(* Logix 5000 project; controller LinePLC1 vendor 1 type 14 code 154 rev 32.11; software revision 32.03; part 2 of 3 *)

ADD_ON_INSTRUCTION FB_ISCCAM_IO_Read   (* revision 1.0, vendor INTRALOX *)
VAR_IN_OUT
   iRawData_Receive : dt_ISCCAM_IO_IN; {required}
   oData_Receive : dt_ISC_CAM_Receive; {required}
END_VAR

ROUTINE Logic   (* ladder *)
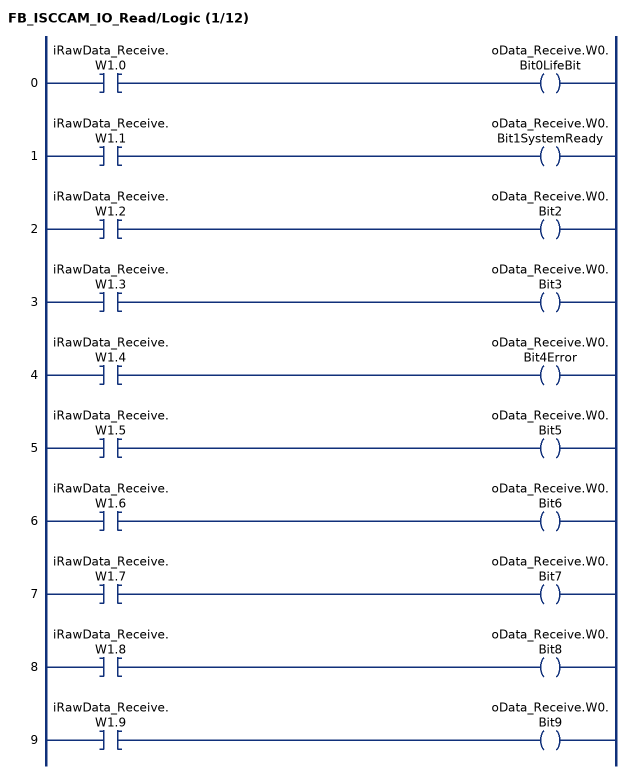
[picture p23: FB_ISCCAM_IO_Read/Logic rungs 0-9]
   0: XIC(iRawData_Receive.W1.0)OTE(oData_Receive.W0.Bit0LifeBit);
   1: XIC(iRawData_Receive.W1.1)OTE(oData_Receive.W0.Bit1SystemReady);
   2: XIC(iRawData_Receive.W1.2)OTE(oData_Receive.W0.Bit2);
   3: XIC(iRawData_Receive.W1.3)OTE(oData_Receive.W0.Bit3);
   4: XIC(iRawData_Receive.W1.4)OTE(oData_Receive.W0.Bit4Error);
   5: XIC(iRawData_Receive.W1.5)OTE(oData_Receive.W0.Bit5);
   6: XIC(iRawData_Receive.W1.6)OTE(oData_Receive.W0.Bit6);
   7: XIC(iRawData_Receive.W1.7)OTE(oData_Receive.W0.Bit7);
   8: XIC(iRawData_Receive.W1.8)OTE(oData_Receive.W0.Bit8);
   9: XIC(iRawData_Receive.W1.9)OTE(oData_Receive.W0.Bit9);
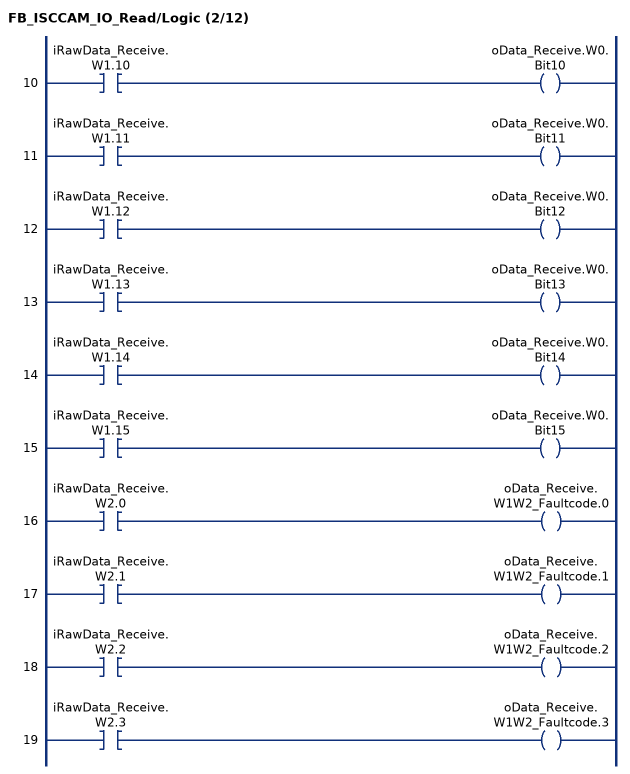
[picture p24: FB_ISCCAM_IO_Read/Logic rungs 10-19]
   10: XIC(iRawData_Receive.W1.10)OTE(oData_Receive.W0.Bit10);
   11: XIC(iRawData_Receive.W1.11)OTE(oData_Receive.W0.Bit11);
   12: XIC(iRawData_Receive.W1.12)OTE(oData_Receive.W0.Bit12);
   13: XIC(iRawData_Receive.W1.13)OTE(oData_Receive.W0.Bit13);
   14: XIC(iRawData_Receive.W1.14)OTE(oData_Receive.W0.Bit14);
   15: XIC(iRawData_Receive.W1.15)OTE(oData_Receive.W0.Bit15);
   16: XIC(iRawData_Receive.W2.0)OTE(oData_Receive.W1W2_Faultcode.0);
   17: XIC(iRawData_Receive.W2.1)OTE(oData_Receive.W1W2_Faultcode.1);
   18: XIC(iRawData_Receive.W2.2)OTE(oData_Receive.W1W2_Faultcode.2);
   19: XIC(iRawData_Receive.W2.3)OTE(oData_Receive.W1W2_Faultcode.3);
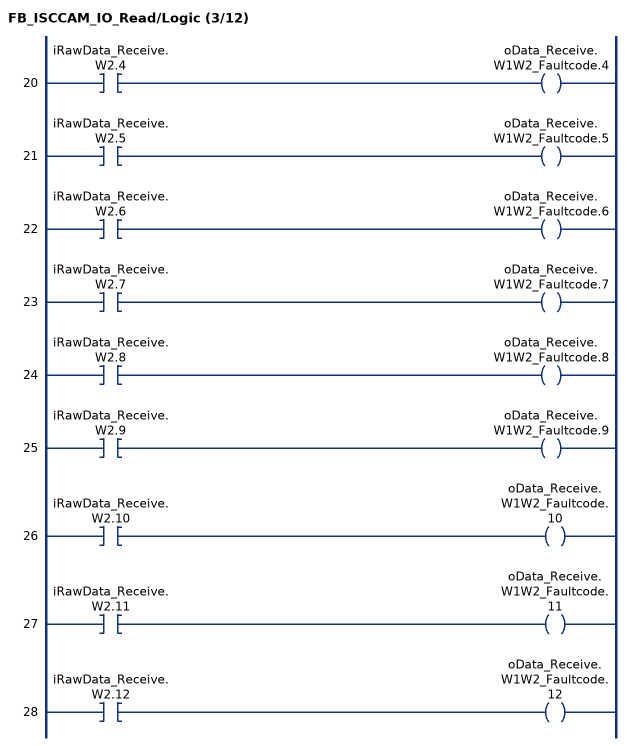
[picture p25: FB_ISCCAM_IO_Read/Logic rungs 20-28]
   20: XIC(iRawData_Receive.W2.4)OTE(oData_Receive.W1W2_Faultcode.4);
   21: XIC(iRawData_Receive.W2.5)OTE(oData_Receive.W1W2_Faultcode.5);
   22: XIC(iRawData_Receive.W2.6)OTE(oData_Receive.W1W2_Faultcode.6);
   23: XIC(iRawData_Receive.W2.7)OTE(oData_Receive.W1W2_Faultcode.7);
   24: XIC(iRawData_Receive.W2.8)OTE(oData_Receive.W1W2_Faultcode.8);
   25: XIC(iRawData_Receive.W2.9)OTE(oData_Receive.W1W2_Faultcode.9);
   26: XIC(iRawData_Receive.W2.10)OTE(oData_Receive.W1W2_Faultcode.10);
   27: XIC(iRawData_Receive.W2.11)OTE(oData_Receive.W1W2_Faultcode.11);
   28: XIC(iRawData_Receive.W2.12)OTE(oData_Receive.W1W2_Faultcode.12);
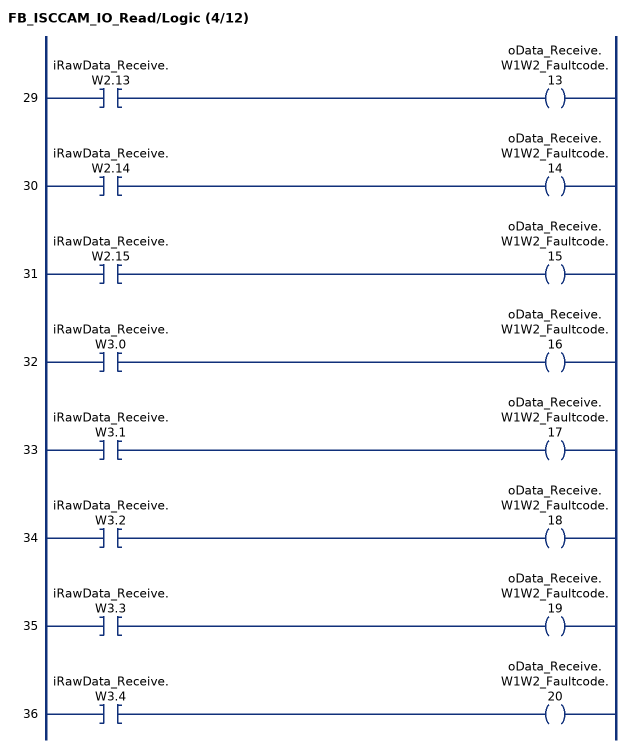
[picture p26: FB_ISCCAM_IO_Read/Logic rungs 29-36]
   29: XIC(iRawData_Receive.W2.13)OTE(oData_Receive.W1W2_Faultcode.13);
   30: XIC(iRawData_Receive.W2.14)OTE(oData_Receive.W1W2_Faultcode.14);
   31: XIC(iRawData_Receive.W2.15)OTE(oData_Receive.W1W2_Faultcode.15);
   32: XIC(iRawData_Receive.W3.0)OTE(oData_Receive.W1W2_Faultcode.16);
   33: XIC(iRawData_Receive.W3.1)OTE(oData_Receive.W1W2_Faultcode.17);
   34: XIC(iRawData_Receive.W3.2)OTE(oData_Receive.W1W2_Faultcode.18);
   35: XIC(iRawData_Receive.W3.3)OTE(oData_Receive.W1W2_Faultcode.19);
   36: XIC(iRawData_Receive.W3.4)OTE(oData_Receive.W1W2_Faultcode.20);
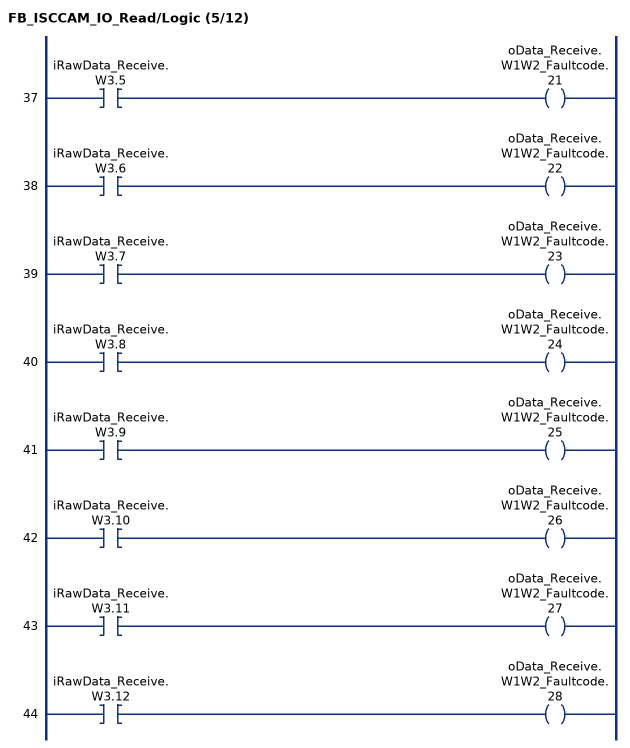
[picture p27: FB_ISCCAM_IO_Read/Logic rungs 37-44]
   37: XIC(iRawData_Receive.W3.5)OTE(oData_Receive.W1W2_Faultcode.21);
   38: XIC(iRawData_Receive.W3.6)OTE(oData_Receive.W1W2_Faultcode.22);
   39: XIC(iRawData_Receive.W3.7)OTE(oData_Receive.W1W2_Faultcode.23);
   40: XIC(iRawData_Receive.W3.8)OTE(oData_Receive.W1W2_Faultcode.24);
   41: XIC(iRawData_Receive.W3.9)OTE(oData_Receive.W1W2_Faultcode.25);
   42: XIC(iRawData_Receive.W3.10)OTE(oData_Receive.W1W2_Faultcode.26);
   43: XIC(iRawData_Receive.W3.11)OTE(oData_Receive.W1W2_Faultcode.27);
   44: XIC(iRawData_Receive.W3.12)OTE(oData_Receive.W1W2_Faultcode.28);
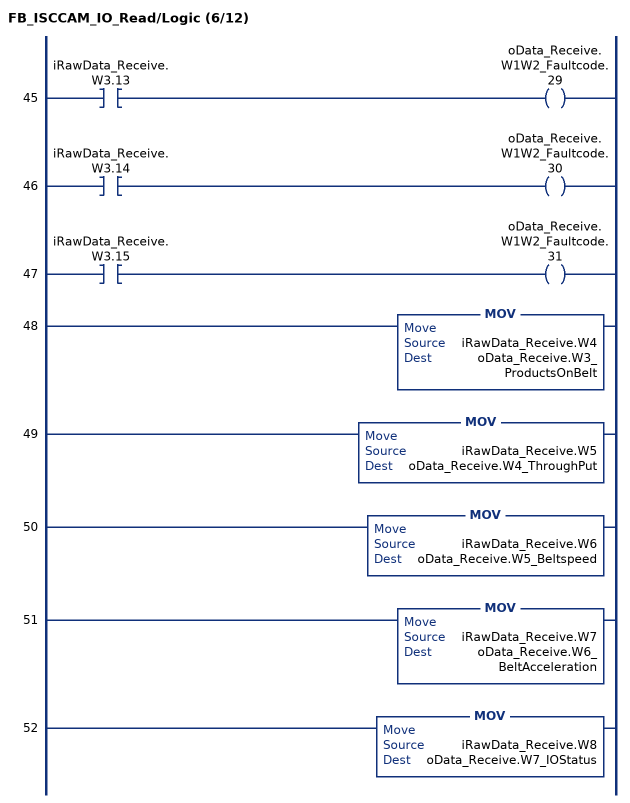
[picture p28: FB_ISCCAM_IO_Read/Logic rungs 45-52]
   45: XIC(iRawData_Receive.W3.13)OTE(oData_Receive.W1W2_Faultcode.29);
   46: XIC(iRawData_Receive.W3.14)OTE(oData_Receive.W1W2_Faultcode.30);
   47: XIC(iRawData_Receive.W3.15)OTE(oData_Receive.W1W2_Faultcode.31);
   48: MOV(iRawData_Receive.W4,oData_Receive.W3_ProductsOnBelt);
   49: MOV(iRawData_Receive.W5,oData_Receive.W4_ThroughPut);
   50: MOV(iRawData_Receive.W6,oData_Receive.W5_Beltspeed);
   51: MOV(iRawData_Receive.W7,oData_Receive.W6_BeltAcceleration);
   52: MOV(iRawData_Receive.W8,oData_Receive.W7_IOStatus);
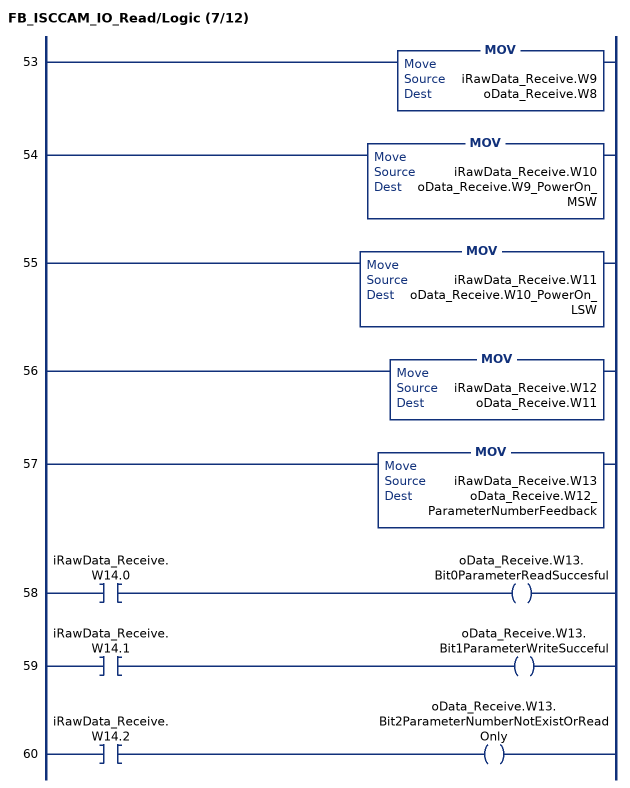
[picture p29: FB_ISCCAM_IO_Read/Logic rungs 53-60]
   53: MOV(iRawData_Receive.W9,oData_Receive.W8);
   54: MOV(iRawData_Receive.W10,oData_Receive.W9_PowerOn_MSW);
   55: MOV(iRawData_Receive.W11,oData_Receive.W10_PowerOn_LSW);
   56: MOV(iRawData_Receive.W12,oData_Receive.W11);
   57: MOV(iRawData_Receive.W13,oData_Receive.W12_ParameterNumberFeedback);
   58: XIC(iRawData_Receive.W14.0)OTE(oData_Receive.W13.Bit0ParameterReadSuccesful);
   59: XIC(iRawData_Receive.W14.1)OTE(oData_Receive.W13.Bit1ParameterWriteSucceful);
   60: XIC(iRawData_Receive.W14.2)OTE(oData_Receive.W13.Bit2ParameterNumberNotExistOrReadOnly);
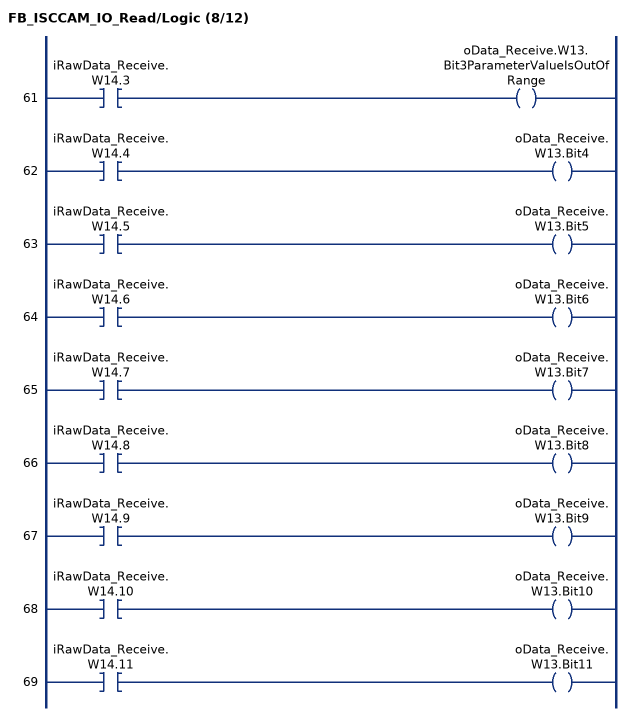
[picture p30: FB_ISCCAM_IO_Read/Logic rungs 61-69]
   61: XIC(iRawData_Receive.W14.3)OTE(oData_Receive.W13.Bit3ParameterValueIsOutOfRange);
   62: XIC(iRawData_Receive.W14.4)OTE(oData_Receive.W13.Bit4);
   63: XIC(iRawData_Receive.W14.5)OTE(oData_Receive.W13.Bit5);
   64: XIC(iRawData_Receive.W14.6)OTE(oData_Receive.W13.Bit6);
   65: XIC(iRawData_Receive.W14.7)OTE(oData_Receive.W13.Bit7);
   66: XIC(iRawData_Receive.W14.8)OTE(oData_Receive.W13.Bit8);
   67: XIC(iRawData_Receive.W14.9)OTE(oData_Receive.W13.Bit9);
   68: XIC(iRawData_Receive.W14.10)OTE(oData_Receive.W13.Bit10);
   69: XIC(iRawData_Receive.W14.11)OTE(oData_Receive.W13.Bit11);
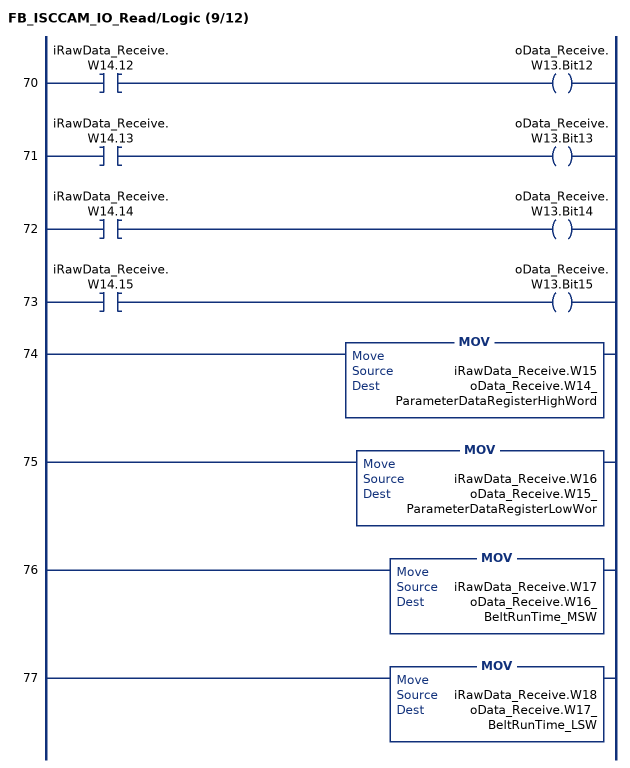
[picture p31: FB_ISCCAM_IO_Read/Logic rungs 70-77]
   70: XIC(iRawData_Receive.W14.12)OTE(oData_Receive.W13.Bit12);
   71: XIC(iRawData_Receive.W14.13)OTE(oData_Receive.W13.Bit13);
   72: XIC(iRawData_Receive.W14.14)OTE(oData_Receive.W13.Bit14);
   73: XIC(iRawData_Receive.W14.15)OTE(oData_Receive.W13.Bit15);
   74: MOV(iRawData_Receive.W15,oData_Receive.W14_ParameterDataRegisterHighWord);
   75: MOV(iRawData_Receive.W16,oData_Receive.W15_ParameterDataRegisterLowWor);
   76: MOV(iRawData_Receive.W17,oData_Receive.W16_BeltRunTime_MSW);
   77: MOV(iRawData_Receive.W18,oData_Receive.W17_BeltRunTime_LSW);
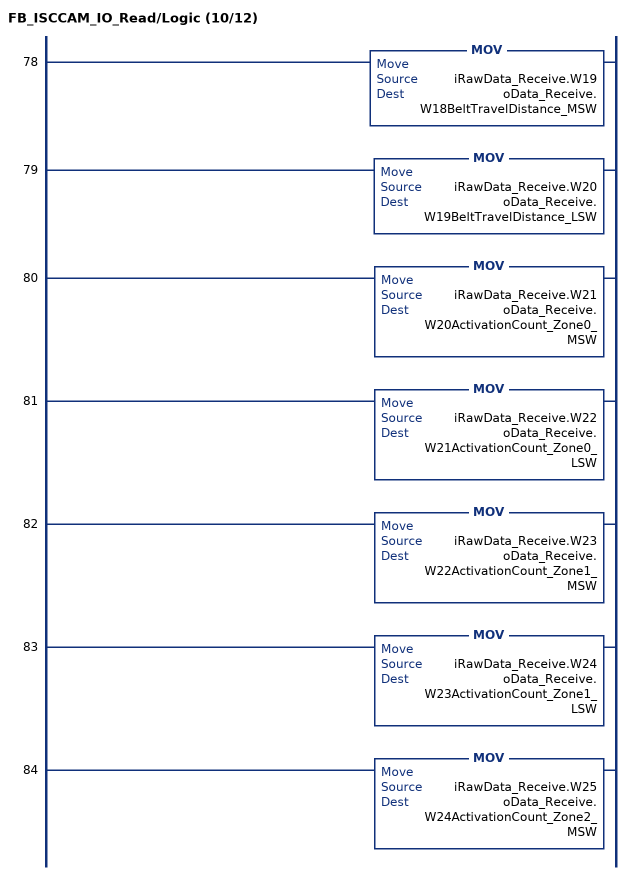
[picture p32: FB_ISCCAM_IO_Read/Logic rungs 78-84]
   78: MOV(iRawData_Receive.W19,oData_Receive.W18BeltTravelDistance_MSW);
   79: MOV(iRawData_Receive.W20,oData_Receive.W19BeltTravelDistance_LSW);
   80: MOV(iRawData_Receive.W21,oData_Receive.W20ActivationCount_Zone0_MSW);
   81: MOV(iRawData_Receive.W22,oData_Receive.W21ActivationCount_Zone0_LSW);
   82: MOV(iRawData_Receive.W23,oData_Receive.W22ActivationCount_Zone1_MSW);
   83: MOV(iRawData_Receive.W24,oData_Receive.W23ActivationCount_Zone1_LSW);
   84: MOV(iRawData_Receive.W25,oData_Receive.W24ActivationCount_Zone2_MSW);
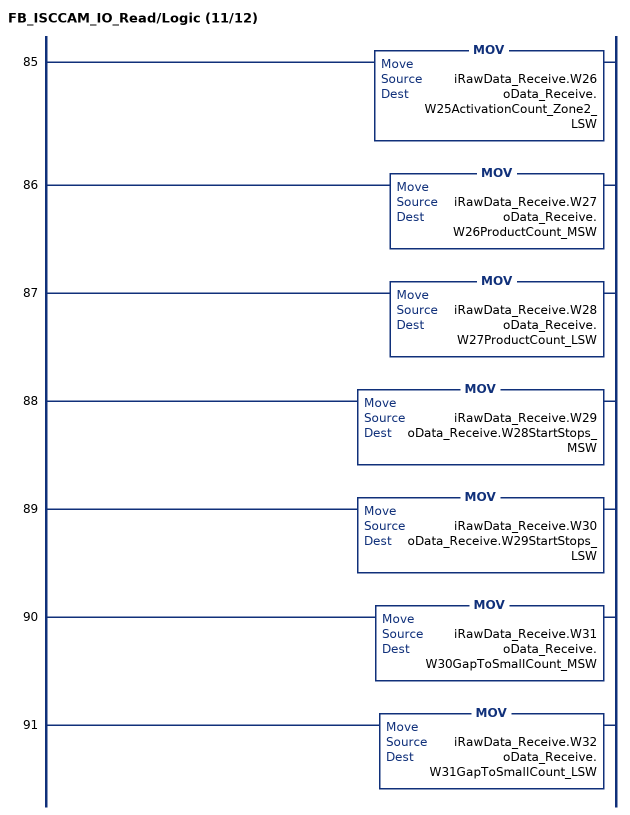
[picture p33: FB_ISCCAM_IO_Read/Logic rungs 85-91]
   85: MOV(iRawData_Receive.W26,oData_Receive.W25ActivationCount_Zone2_LSW);
   86: MOV(iRawData_Receive.W27,oData_Receive.W26ProductCount_MSW);
   87: MOV(iRawData_Receive.W28,oData_Receive.W27ProductCount_LSW);
   88: MOV(iRawData_Receive.W29,oData_Receive.W28StartStops_MSW);
   89: MOV(iRawData_Receive.W30,oData_Receive.W29StartStops_LSW);
   90: MOV(iRawData_Receive.W31,oData_Receive.W30GapToSmallCount_MSW);
   91: MOV(iRawData_Receive.W32,oData_Receive.W31GapToSmallCount_LSW);
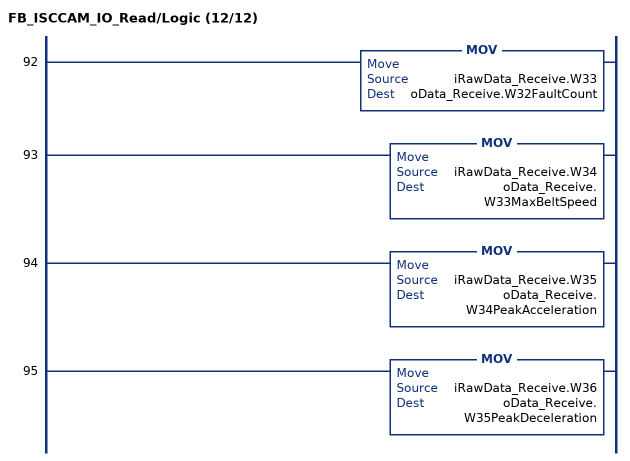
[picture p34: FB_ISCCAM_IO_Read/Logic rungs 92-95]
   92: MOV(iRawData_Receive.W33,oData_Receive.W32FaultCount);
   93: MOV(iRawData_Receive.W34,oData_Receive.W33MaxBeltSpeed);
   94: MOV(iRawData_Receive.W35,oData_Receive.W34PeakAcceleration);
   95: MOV(iRawData_Receive.W36,oData_Receive.W35PeakDeceleration);
END_ROUTINE
END_ADD_ON_INSTRUCTION

ADD_ON_INSTRUCTION FB_ISCCAM_IO_Write   (* revision 1.0, vendor INTRALOX *)
VAR_IN_OUT
   oRawData_Send : dt_ISCCAM_IO_OUT; {required}
   iData_Send : dt_ISC_CAM_Send; {required}
END_VAR

ROUTINE Logic   (* ladder *)
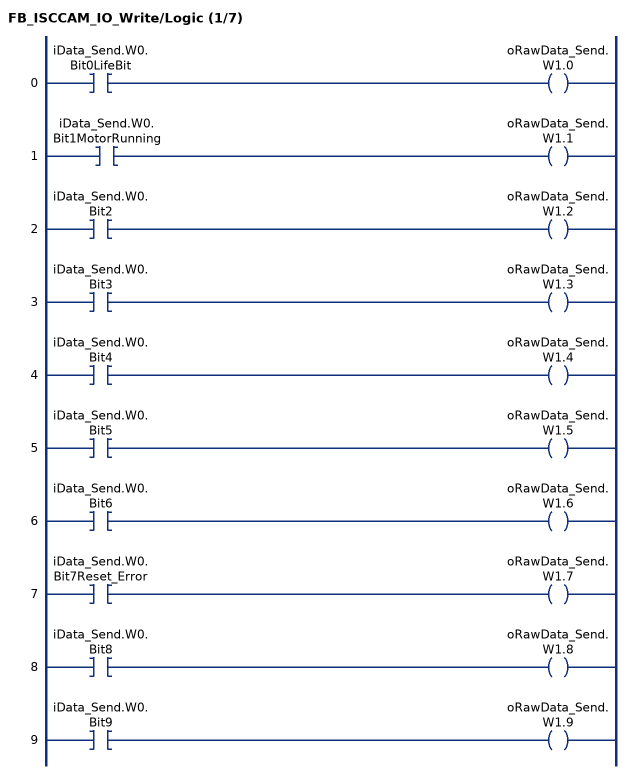
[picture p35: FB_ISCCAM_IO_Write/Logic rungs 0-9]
   0: XIC(iData_Send.W0.Bit0LifeBit)OTE(oRawData_Send.W1.0);
   1: XIC(iData_Send.W0.Bit1MotorRunning)OTE(oRawData_Send.W1.1);
   2: XIC(iData_Send.W0.Bit2)OTE(oRawData_Send.W1.2);
   3: XIC(iData_Send.W0.Bit3)OTE(oRawData_Send.W1.3);
   4: XIC(iData_Send.W0.Bit4)OTE(oRawData_Send.W1.4);
   5: XIC(iData_Send.W0.Bit5)OTE(oRawData_Send.W1.5);
   6: XIC(iData_Send.W0.Bit6)OTE(oRawData_Send.W1.6);
   7: XIC(iData_Send.W0.Bit7Reset_Error)OTE(oRawData_Send.W1.7);
   8: XIC(iData_Send.W0.Bit8)OTE(oRawData_Send.W1.8);
   9: XIC(iData_Send.W0.Bit9)OTE(oRawData_Send.W1.9);
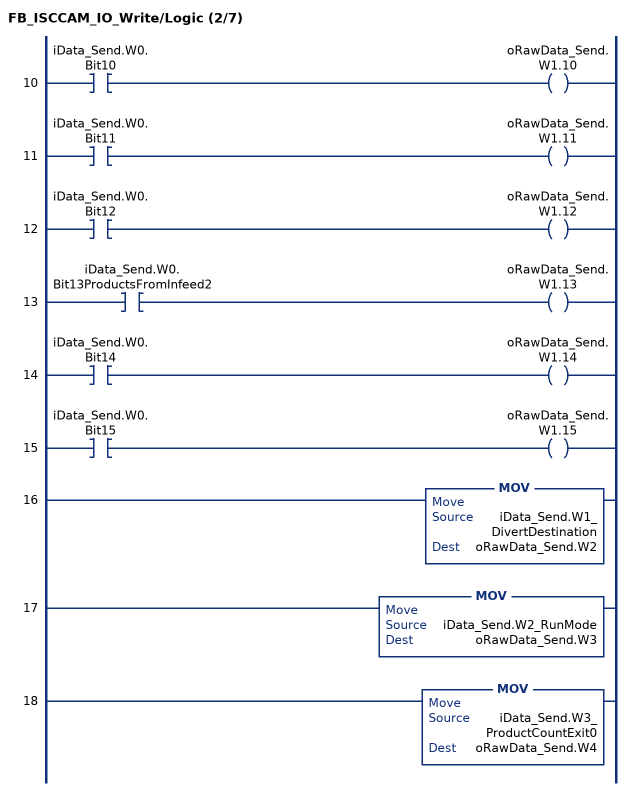
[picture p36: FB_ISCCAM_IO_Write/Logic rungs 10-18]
   10: XIC(iData_Send.W0.Bit10)OTE(oRawData_Send.W1.10);
   11: XIC(iData_Send.W0.Bit11)OTE(oRawData_Send.W1.11);
   12: XIC(iData_Send.W0.Bit12)OTE(oRawData_Send.W1.12);
   13: XIC(iData_Send.W0.Bit13ProductsFromInfeed2)OTE(oRawData_Send.W1.13);
   14: XIC(iData_Send.W0.Bit14)OTE(oRawData_Send.W1.14);
   15: XIC(iData_Send.W0.Bit15)OTE(oRawData_Send.W1.15);
   16: MOV(iData_Send.W1_DivertDestination,oRawData_Send.W2);
   17: MOV(iData_Send.W2_RunMode,oRawData_Send.W3);
   18: MOV(iData_Send.W3_ProductCountExit0,oRawData_Send.W4);
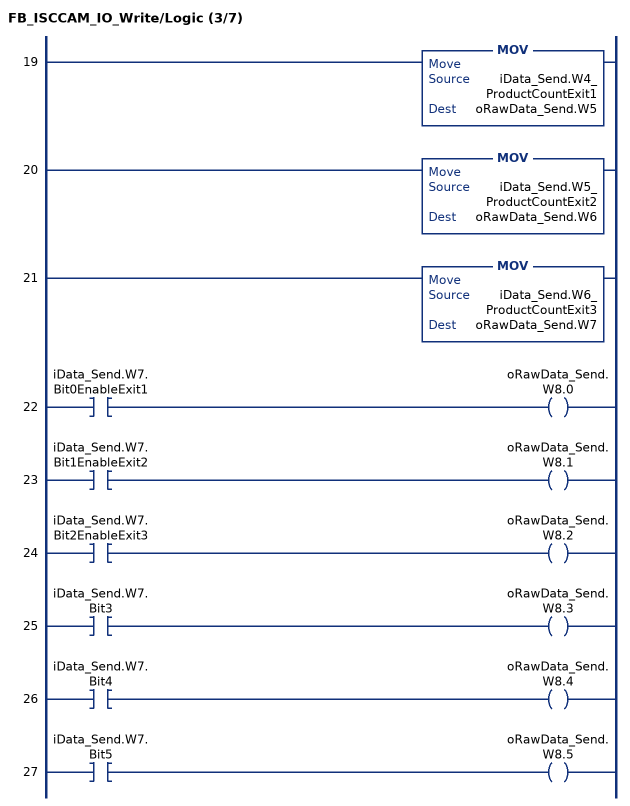
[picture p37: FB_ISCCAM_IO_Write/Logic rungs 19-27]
   19: MOV(iData_Send.W4_ProductCountExit1,oRawData_Send.W5);
   20: MOV(iData_Send.W5_ProductCountExit2,oRawData_Send.W6);
   21: MOV(iData_Send.W6_ProductCountExit3,oRawData_Send.W7);
   22: XIC(iData_Send.W7.Bit0EnableExit1)OTE(oRawData_Send.W8.0);
   23: XIC(iData_Send.W7.Bit1EnableExit2)OTE(oRawData_Send.W8.1);
   24: XIC(iData_Send.W7.Bit2EnableExit3)OTE(oRawData_Send.W8.2);
   25: XIC(iData_Send.W7.Bit3)OTE(oRawData_Send.W8.3);
   26: XIC(iData_Send.W7.Bit4)OTE(oRawData_Send.W8.4);
   27: XIC(iData_Send.W7.Bit5)OTE(oRawData_Send.W8.5);
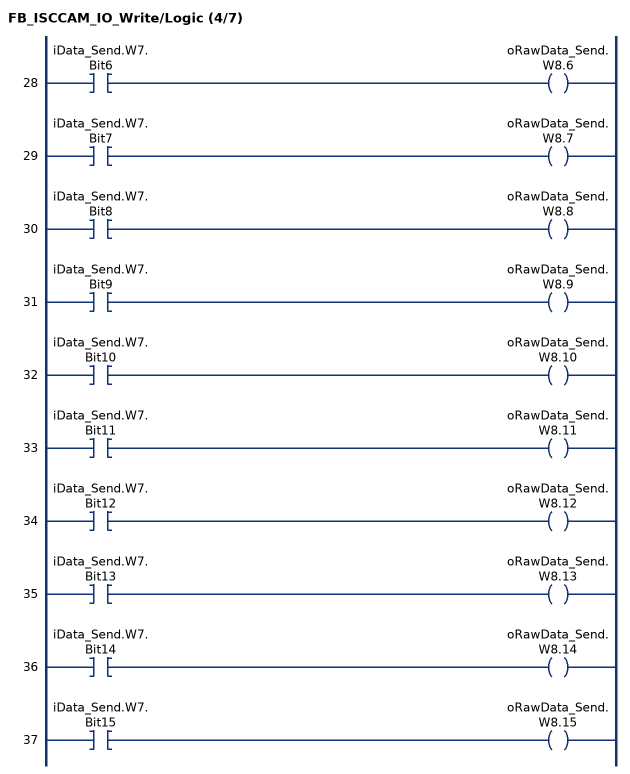
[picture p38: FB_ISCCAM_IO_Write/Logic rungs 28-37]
   28: XIC(iData_Send.W7.Bit6)OTE(oRawData_Send.W8.6);
   29: XIC(iData_Send.W7.Bit7)OTE(oRawData_Send.W8.7);
   30: XIC(iData_Send.W7.Bit8)OTE(oRawData_Send.W8.8);
   31: XIC(iData_Send.W7.Bit9)OTE(oRawData_Send.W8.9);
   32: XIC(iData_Send.W7.Bit10)OTE(oRawData_Send.W8.10);
   33: XIC(iData_Send.W7.Bit11)OTE(oRawData_Send.W8.11);
   34: XIC(iData_Send.W7.Bit12)OTE(oRawData_Send.W8.12);
   35: XIC(iData_Send.W7.Bit13)OTE(oRawData_Send.W8.13);
   36: XIC(iData_Send.W7.Bit14)OTE(oRawData_Send.W8.14);
   37: XIC(iData_Send.W7.Bit15)OTE(oRawData_Send.W8.15);
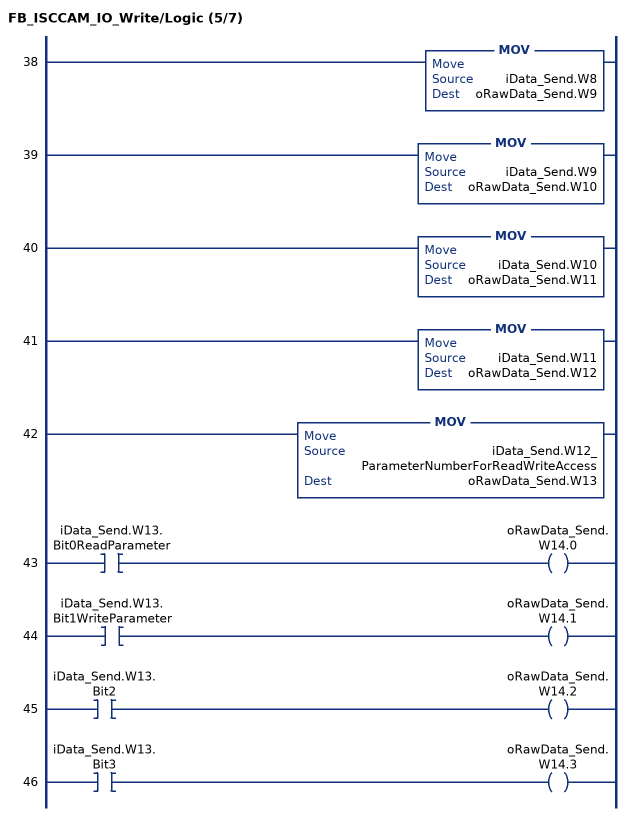
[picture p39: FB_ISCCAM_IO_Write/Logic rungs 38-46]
   38: MOV(iData_Send.W8,oRawData_Send.W9);
   39: MOV(iData_Send.W9,oRawData_Send.W10);
   40: MOV(iData_Send.W10,oRawData_Send.W11);
   41: MOV(iData_Send.W11,oRawData_Send.W12);
   42: MOV(iData_Send.W12_ParameterNumberForReadWriteAccess,oRawData_Send.W13);
   43: XIC(iData_Send.W13.Bit0ReadParameter)OTE(oRawData_Send.W14.0);
   44: XIC(iData_Send.W13.Bit1WriteParameter)OTE(oRawData_Send.W14.1);
   45: XIC(iData_Send.W13.Bit2)OTE(oRawData_Send.W14.2);
   46: XIC(iData_Send.W13.Bit3)OTE(oRawData_Send.W14.3);
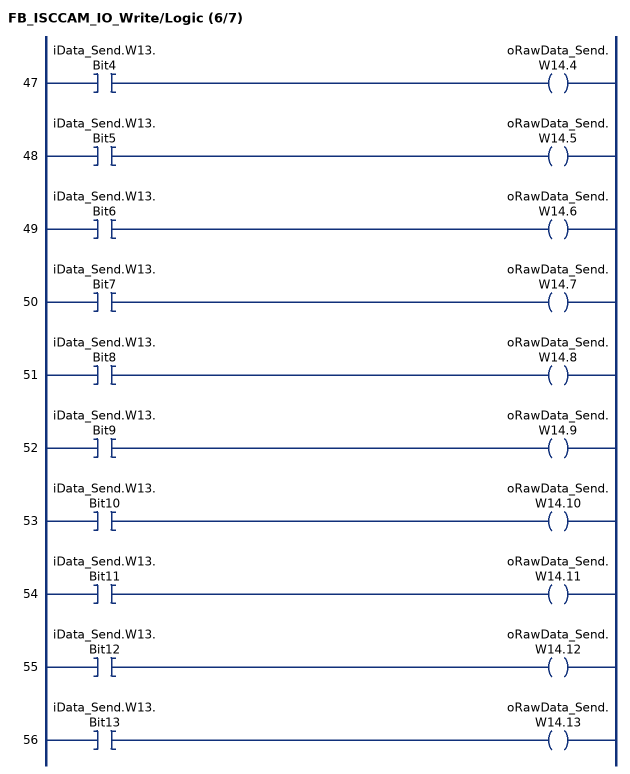
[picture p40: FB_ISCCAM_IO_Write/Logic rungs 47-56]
   47: XIC(iData_Send.W13.Bit4)OTE(oRawData_Send.W14.4);
   48: XIC(iData_Send.W13.Bit5)OTE(oRawData_Send.W14.5);
   49: XIC(iData_Send.W13.Bit6)OTE(oRawData_Send.W14.6);
   50: XIC(iData_Send.W13.Bit7)OTE(oRawData_Send.W14.7);
   51: XIC(iData_Send.W13.Bit8)OTE(oRawData_Send.W14.8);
   52: XIC(iData_Send.W13.Bit9)OTE(oRawData_Send.W14.9);
   53: XIC(iData_Send.W13.Bit10)OTE(oRawData_Send.W14.10);
   54: XIC(iData_Send.W13.Bit11)OTE(oRawData_Send.W14.11);
   55: XIC(iData_Send.W13.Bit12)OTE(oRawData_Send.W14.12);
   56: XIC(iData_Send.W13.Bit13)OTE(oRawData_Send.W14.13);
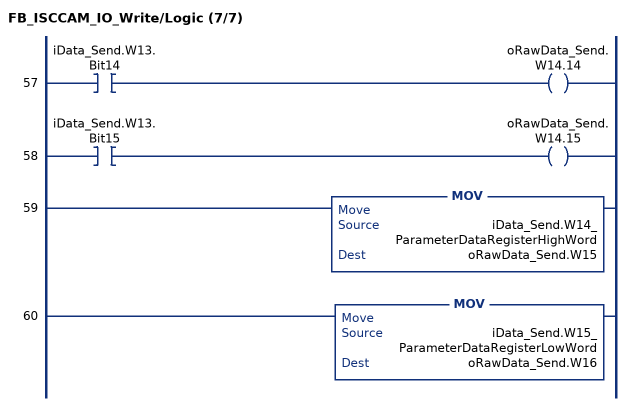
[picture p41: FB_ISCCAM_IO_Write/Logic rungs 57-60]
   57: XIC(iData_Send.W13.Bit14)OTE(oRawData_Send.W14.14);
   58: XIC(iData_Send.W13.Bit15)OTE(oRawData_Send.W14.15);
   59: MOV(iData_Send.W14_ParameterDataRegisterHighWord,oRawData_Send.W15);
   60: MOV(iData_Send.W15_ParameterDataRegisterLowWord,oRawData_Send.W16);
END_ROUTINE
END_ADD_ON_INSTRUCTION
